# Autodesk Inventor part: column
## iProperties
Shininess: 64.0
Length Units: 11272
Angle Units: 11279
Time Units: 11290
Mass Units: 11286
Length Display Precision: 3
Angle Display Precision: 2
Compacted: True
Part Number: column
Document SubType Name: Modeling
Created: 2002-11
Designer: Elise Moss
Density: 0.0
Volumn: 0.0
Area: 0.0
PropertySet Name: Model Information
Control State: 0
Master: False
Checked Out: False
Author: Elise Moss
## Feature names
1. Extrusion1
2. Shell1
